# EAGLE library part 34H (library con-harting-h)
CONNECTOR
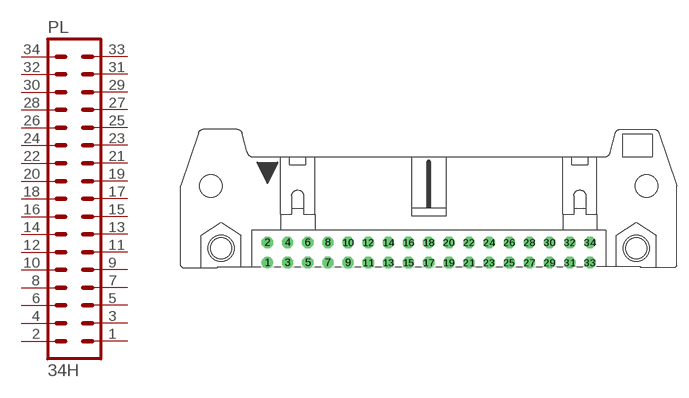
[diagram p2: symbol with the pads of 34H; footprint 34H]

Designator prefix PL

## 34H (OC_FARNELL: unknown; OC_NEWARK: unknown)  [34H]
1  1  pas
2  2  pas
3  3  pas
4  4  pas
5  5  pas
6  6  pas
7  7  pas
8  8  pas
9  9  pas
10  10  pas
11  11  pas
12  12  pas
13  13  pas
14  14  pas
15  15  pas
16  16  pas
17  17  pas
18  18  pas
19  19  pas
20  20  pas
21  21  pas
22  22  pas
23  23  pas
24  24  pas
25  25  pas
26  26  pas
27  27  pas
28  28  pas
29  29  pas
30  30  pas
31  31  pas
32  32  pas
33  33  pas
34  34  pas

## Footprint 34H (pad centres in mm)
CONNECTOR
drill 0.914 round: 1 -20.32,-1.27
drill 0.914 octagon: 2 -20.32,1.27; 3 -17.78,-1.27; 4 -17.78,1.27; 5 -15.24,-1.27; 6 -15.24,1.27; 7 -12.7,-1.27; 8 -12.7,1.27; 9 -10.16,-1.27; 10 -10.16,1.27; 11 -7.62,-1.27; 12 -7.62,1.27; 13 -5.08,-1.27; 14 -5.08,1.27; 15 -2.54,-1.27; 16 -2.54,1.27; 17 0,-1.27; 18 0,1.27; 19 2.54,-1.27; 20 2.54,1.27; 21 5.08,-1.27; 22 5.08,1.27; 23 7.62,-1.27; 24 7.62,1.27; 25 10.16,-1.27; 26 10.16,1.27; 27 12.7,-1.27; 28 12.7,1.27; 29 15.24,-1.27; 30 15.24,1.27; 31 17.78,-1.27; 32 17.78,1.27; 33 20.32,-1.27; 34 20.32,1.27
hole 3.302 at -26.162,0.533
hole 3.302 at 26.162,0.533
